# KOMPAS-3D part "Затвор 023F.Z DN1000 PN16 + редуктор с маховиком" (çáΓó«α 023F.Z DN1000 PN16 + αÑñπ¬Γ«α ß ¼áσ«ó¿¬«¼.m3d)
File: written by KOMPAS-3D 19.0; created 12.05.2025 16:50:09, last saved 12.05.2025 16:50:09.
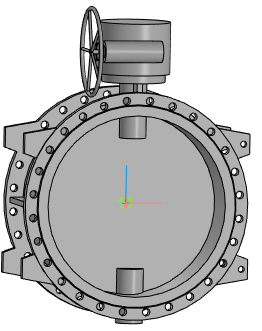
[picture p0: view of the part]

Document properties: Полное имя файла: Затвор 023F.Z DN1000 PN16 + редуктор с маховиком.a3d

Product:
- Part/product: Затвор 023F.Z DN1000 PN16 + редуктор с маховиком
    Масса: 1601.26

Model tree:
1. Операция без истории:1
